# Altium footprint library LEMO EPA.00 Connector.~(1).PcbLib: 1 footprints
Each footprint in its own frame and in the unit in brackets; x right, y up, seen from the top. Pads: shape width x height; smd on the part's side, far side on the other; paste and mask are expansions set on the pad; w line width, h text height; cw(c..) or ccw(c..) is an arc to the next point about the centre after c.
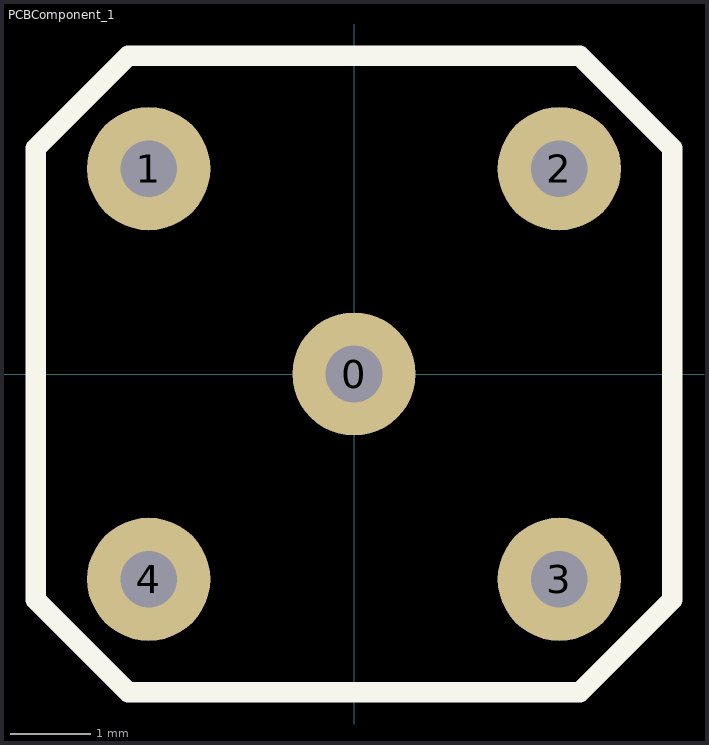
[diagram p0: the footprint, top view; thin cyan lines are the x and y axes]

## PCBComponent_1 [mil]
pads (5):
  round 60 hole 27.56: 0(0,0) 1(-100,100) 2(100,100) 3(100,-100) 4(-100,-100)
Top Overlay:
  lines w10: -155,-110 -110,-155 110,-155 155,-110 155,110 110,155 -110,155 -155,110 -155,-110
